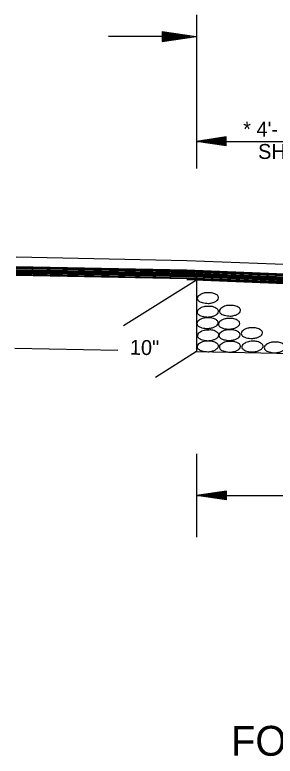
# Model space of a CAD drawing. Extents: x 1929624 to 1936506, y 596315 to 605721.
# Drawn here: x 1933789.9 to 1933894.6, y 603512.5 to 603810.2 of the extents above; entities that cross this region are included whole.
import ezdxf

# ---------------------------------------------------------------- set-up
doc = ezdxf.new("R2010")
doc.units = 0
doc.layers.add('Default', color=7, linetype='Continuous')

msp = doc.modelspace()

# ---------------------------------------------------------------- linework, layer by layer
at = {"layer": 'Default'}
for p, q in [((1933862.89, 603810.24), (1933862.89, 603748.47)), ((1933849.17, 603803.61), (1933862.87, 603801.57)), ((1933849.17, 603803.61), (1933849.17, 603799.51)), ((1933849.17, 603803.28), (1933860.6, 603801.57)), ((1933849.17, 603802.93), (1933858.23, 603801.57)), ((1933849.17, 603802.6), (1933855.95, 603801.57)), ((1933849.17, 603802.21), (1933853.63, 603801.57)), ((1933849.17, 603801.9), (1933851.36, 603801.57)), ((1933860.6, 603801.57), (1933827.56, 603801.57)), ((1933849.17, 603799.51), (1933862.87, 603801.57)), ((1933849.17, 603800.89), (1933853.63, 603801.57)), ((1933849.17, 603800.2), (1933858.23, 603801.57)), ((1933849.17, 603799.86), (1933860.6, 603801.57)), ((1933849.17, 603800.56), (1933855.95, 603801.57)), ((1933849.17, 603801.24), (1933851.36, 603801.57)), ((1933874.89, 603761.18), (1933862.89, 603759.38)), ((1933874.89, 603760.88), (1933864.89, 603759.38)), ((1933874.89, 603760.57), (1933866.96, 603759.38)), ((1933874.89, 603760.27), (1933868.96, 603759.38)), ((1933874.89, 603757.58), (1933874.89, 603761.18)), ((1933862.89, 603759.38), (1934041.58, 603759.38)), ((1933874.89, 603757.58), (1933862.89, 603759.38)), ((1933874.89, 603757.88), (1933864.89, 603759.38)), ((1933874.89, 603758.19), (1933866.96, 603759.38)), ((1933874.89, 603758.49), (1933868.96, 603759.38)), ((1933874.89, 603759.97), (1933870.99, 603759.38)), ((1933874.89, 603758.8), (1933870.99, 603759.38)), ((1933874.89, 603759.66), (1933872.99, 603759.38)), ((1933874.89, 603759.1), (1933872.99, 603759.38)), ((1933790.46, 603713), (1933859.07, 603711.63)), ((1933859.07, 603711.63), (1934041.46, 603704.32)), ((1933790.46, 603709.18), (1933859.07, 603707.83)), ((1933790.46, 603708.76), (1933859.07, 603707.39)), ((1933790.46, 603708.44), (1933859.07, 603707.06)), ((1933790.46, 603708.03), (1933859.07, 603706.64)), ((1933790.46, 603707.63), (1933859.07, 603706.22)), ((1933790.46, 603707.25), (1933859.07, 603705.86)), ((1933790.46, 603706.86), (1933859.07, 603705.48)), ((1933859.07, 603707.83), (1934041.3, 603700.5)), ((1933859.07, 603707.39), (1934041.58, 603700.05)), ((1933859.07, 603707.06), (1934041.77, 603699.76)), ((1933859.07, 603706.64), (1934042.08, 603699.3)), ((1933862.98, 603707.68), (1933862.98, 603674.97)), ((1933790.46, 603706.47), (1933859.07, 603705.1)), ((1933790.46, 603706.04), (1933859.07, 603704.68)), ((1933790.46, 603705.66), (1933859.07, 603704.31)), ((1933863.02, 603703.63), (1933833.59, 603685.29)), ((1933859.07, 603706.22), (1934042.3, 603698.9)), ((1933859.07, 603705.86), (1934042.58, 603698.46)), ((1933859.07, 603705.48), (1934042.8, 603698.12)), ((1933859.07, 603705.1), (1934043.12, 603697.68)), ((1933859.07, 603704.68), (1934043.36, 603697.28)), ((1933859.07, 603704.31), (1934043.62, 603696.84)), ((1933859.07, 603703.98), (1934043.79, 603696.56)), ((1933789.88, 603676.44), (1933831.36, 603675.61)), ((1933862.98, 603674.97), (1933846.44, 603664.66)), ((1933862.98, 603674.97), (1934265.9, 603666.92)), ((1933862.98, 603633.89), (1933862.98, 603600.53)), ((1933874.98, 603619.01), (1933862.98, 603617.21)), ((1933862.98, 603617.21), (1934060, 603617.21)), ((1933874.98, 603615.41), (1933862.98, 603617.21)), ((1933874.98, 603618.71), (1933864.98, 603617.21)), ((1933874.98, 603615.71), (1933864.98, 603617.21)), ((1933874.98, 603618.4), (1933867.05, 603617.21)), ((1933874.98, 603616.02), (1933867.05, 603617.21)), ((1933874.98, 603618.1), (1933869.05, 603617.21)), ((1933874.98, 603616.32), (1933869.05, 603617.21)), ((1933874.98, 603617.8), (1933871.08, 603617.21)), ((1933874.98, 603616.63), (1933871.08, 603617.21)), ((1933874.98, 603617.49), (1933873.08, 603617.21)), ((1933874.98, 603616.93), (1933873.08, 603617.21)), ((1933874.98, 603615.41), (1933874.98, 603619.01))]:
    msp.add_line(p, q, dxfattribs=at)
for points in [[(1933867.48, 603698.62), (1933869.01, 603698.61), (1933870.83, 603697.97), (1933871.72, 603697.14), (1933871.84, 603696.6), (1933871.38, 603695.68), (1933870.86, 603695.29), (1933869.86, 603694.77), (1933868.4, 603694.43), (1933867.64, 603694.35), (1933866.53, 603694.46), (1933865.27, 603694.67), (1933864.32, 603695.04), (1933863.44, 603695.77), (1933863.29, 603696.35), (1933863.55, 603697.17), (1933864.25, 603697.7), (1933864.89, 603698.12), (1933865.91, 603698.47), (1933866.54, 603698.61), (1933867.48, 603698.62)], [(1933867.44, 603693.14), (1933868.97, 603693.13), (1933870.79, 603692.49), (1933871.68, 603691.66), (1933871.8, 603691.12), (1933871.34, 603690.2), (1933870.82, 603689.81), (1933869.82, 603689.29), (1933868.36, 603688.95), (1933867.6, 603688.87), (1933866.49, 603688.98), (1933865.23, 603689.19), (1933864.28, 603689.56), (1933863.4, 603690.29), (1933863.25, 603690.87), (1933863.51, 603691.69), (1933864.21, 603692.22), (1933864.85, 603692.64), (1933865.87, 603692.99), (1933866.5, 603693.13), (1933867.44, 603693.14)], [(1933876.34, 603693.53), (1933877.87, 603693.52), (1933879.69, 603692.88), (1933880.58, 603692.05), (1933880.7, 603691.51), (1933880.24, 603690.59), (1933879.72, 603690.2), (1933878.72, 603689.68), (1933877.26, 603689.34), (1933876.5, 603689.26), (1933875.39, 603689.37), (1933874.13, 603689.58), (1933873.18, 603689.95), (1933872.3, 603690.68), (1933872.15, 603691.26), (1933872.41, 603692.08), (1933873.11, 603692.61), (1933873.75, 603693.03), (1933874.77, 603693.38), (1933875.4, 603693.52), (1933876.34, 603693.53)], [(1933867.32, 603688.54), (1933868.85, 603688.53), (1933870.67, 603687.89), (1933871.56, 603687.06), (1933871.68, 603686.52), (1933871.22, 603685.6), (1933870.7, 603685.21), (1933869.7, 603684.69), (1933868.24, 603684.35), (1933867.48, 603684.27), (1933866.37, 603684.38), (1933865.11, 603684.59), (1933864.16, 603684.96), (1933863.28, 603685.69), (1933863.13, 603686.27), (1933863.39, 603687.09), (1933864.09, 603687.62), (1933864.73, 603688.04), (1933865.75, 603688.39), (1933866.38, 603688.53), (1933867.32, 603688.54)], [(1933875.98, 603688.27), (1933877.51, 603688.26), (1933879.33, 603687.62), (1933880.22, 603686.79), (1933880.34, 603686.25), (1933879.88, 603685.33), (1933879.36, 603684.94), (1933878.36, 603684.42), (1933876.9, 603684.08), (1933876.14, 603684), (1933875.03, 603684.11), (1933873.77, 603684.32), (1933872.82, 603684.69), (1933871.94, 603685.42), (1933871.79, 603686), (1933872.05, 603686.82), (1933872.75, 603687.35), (1933873.39, 603687.77), (1933874.41, 603688.12), (1933875.04, 603688.26), (1933875.98, 603688.27)], [(1933867.57, 603683.65), (1933869.1, 603683.64), (1933870.92, 603683), (1933871.81, 603682.17), (1933871.93, 603681.63), (1933871.47, 603680.71), (1933870.95, 603680.32), (1933869.95, 603679.8), (1933868.49, 603679.46), (1933867.73, 603679.38), (1933866.62, 603679.49), (1933865.36, 603679.7), (1933864.41, 603680.07), (1933863.53, 603680.8), (1933863.38, 603681.38), (1933863.64, 603682.2), (1933864.34, 603682.73), (1933864.98, 603683.15), (1933866, 603683.5), (1933866.63, 603683.64), (1933867.57, 603683.65)], [(1933876.17, 603683.73), (1933877.7, 603683.72), (1933879.52, 603683.08), (1933880.41, 603682.25), (1933880.53, 603681.71), (1933880.07, 603680.79), (1933879.55, 603680.4), (1933878.55, 603679.88), (1933877.09, 603679.54), (1933876.33, 603679.46), (1933875.22, 603679.57), (1933873.96, 603679.78), (1933873.01, 603680.15), (1933872.13, 603680.88), (1933871.98, 603681.46), (1933872.24, 603682.28), (1933872.94, 603682.81), (1933873.58, 603683.23), (1933874.6, 603683.58), (1933875.23, 603683.72), (1933876.17, 603683.73)], [(1933885.14, 603684.52), (1933886.67, 603684.51), (1933888.49, 603683.87), (1933889.38, 603683.04), (1933889.5, 603682.5), (1933889.04, 603681.58), (1933888.52, 603681.19), (1933887.52, 603680.67), (1933886.06, 603680.33), (1933885.3, 603680.25), (1933884.19, 603680.36), (1933882.93, 603680.57), (1933881.98, 603680.94), (1933881.1, 603681.67), (1933880.95, 603682.25), (1933881.21, 603683.07), (1933881.91, 603683.6), (1933882.55, 603684.02), (1933883.57, 603684.37), (1933884.2, 603684.51), (1933885.14, 603684.52)], [(1933867.41, 603679.21), (1933868.94, 603679.2), (1933870.76, 603678.56), (1933871.65, 603677.73), (1933871.77, 603677.19), (1933871.31, 603676.27), (1933870.79, 603675.88), (1933869.79, 603675.36), (1933868.33, 603675.02), (1933867.57, 603674.94), (1933866.46, 603675.05), (1933865.2, 603675.26), (1933864.25, 603675.63), (1933863.37, 603676.36), (1933863.22, 603676.94), (1933863.48, 603677.76), (1933864.18, 603678.29), (1933864.82, 603678.71), (1933865.84, 603679.06), (1933866.47, 603679.2), (1933867.41, 603679.21)], [(1933876.33, 603679.07), (1933877.86, 603679.06), (1933879.68, 603678.42), (1933880.57, 603677.59), (1933880.69, 603677.05), (1933880.23, 603676.13), (1933879.71, 603675.74), (1933878.71, 603675.22), (1933877.25, 603674.88), (1933876.49, 603674.8), (1933875.38, 603674.91), (1933874.12, 603675.12), (1933873.17, 603675.49), (1933872.29, 603676.22), (1933872.14, 603676.8), (1933872.4, 603677.62), (1933873.1, 603678.15), (1933873.74, 603678.57), (1933874.76, 603678.92), (1933875.39, 603679.06), (1933876.33, 603679.07)], [(1933885.4, 603679.12), (1933886.93, 603679.11), (1933888.75, 603678.47), (1933889.64, 603677.64), (1933889.76, 603677.1), (1933889.3, 603676.18), (1933888.78, 603675.79), (1933887.78, 603675.27), (1933886.32, 603674.93), (1933885.56, 603674.85), (1933884.45, 603674.96), (1933883.19, 603675.17), (1933882.24, 603675.54), (1933881.36, 603676.27), (1933881.21, 603676.85), (1933881.47, 603677.67), (1933882.17, 603678.2), (1933882.81, 603678.62), (1933883.83, 603678.97), (1933884.46, 603679.11), (1933885.4, 603679.12)], [(1933894.39, 603678.8), (1933895.92, 603678.79), (1933897.74, 603678.15), (1933898.63, 603677.32), (1933898.75, 603676.78), (1933898.29, 603675.86), (1933897.77, 603675.47), (1933896.77, 603674.95), (1933895.31, 603674.61), (1933894.55, 603674.53), (1933893.44, 603674.64), (1933892.18, 603674.85), (1933891.23, 603675.22), (1933890.35, 603675.95), (1933890.2, 603676.53), (1933890.46, 603677.35), (1933891.16, 603677.88), (1933891.8, 603678.3), (1933892.82, 603678.65), (1933893.45, 603678.79), (1933894.39, 603678.8)]]:
    msp.add_spline(points, degree=3, dxfattribs=at)

# ---------------------------------------------------------------- texts
for s, height, p in [('* 4\'- 0" TRENCHING AND ', 6, (1933881.73, 603761.36)), ('SHOULDER PREP. WIDTH ', 6, (1933887.73, 603752.36)), ('FOR MAINTENANCE OF TRAFFIC', 12, (1933876.83, 603512.69))]:
    msp.add_text(s, height=height, dxfattribs=at).set_placement(p)
msp.add_text('10"', height=6, rotation=358.8543, dxfattribs=at).set_placement((1933836.1, 603673.76))

doc.saveas('drawing.dxf')
